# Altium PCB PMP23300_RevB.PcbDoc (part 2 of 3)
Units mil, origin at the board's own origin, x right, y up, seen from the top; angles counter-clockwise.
Board outline 3834 x 2383 mil, 4 copper layers (Top Layer 1, Signal Layer 2, Signal Layer 3, Bottom Layer 1), stack 70.112 mil thick; 203 components, 126 nets, 635 pads, 226 vias.
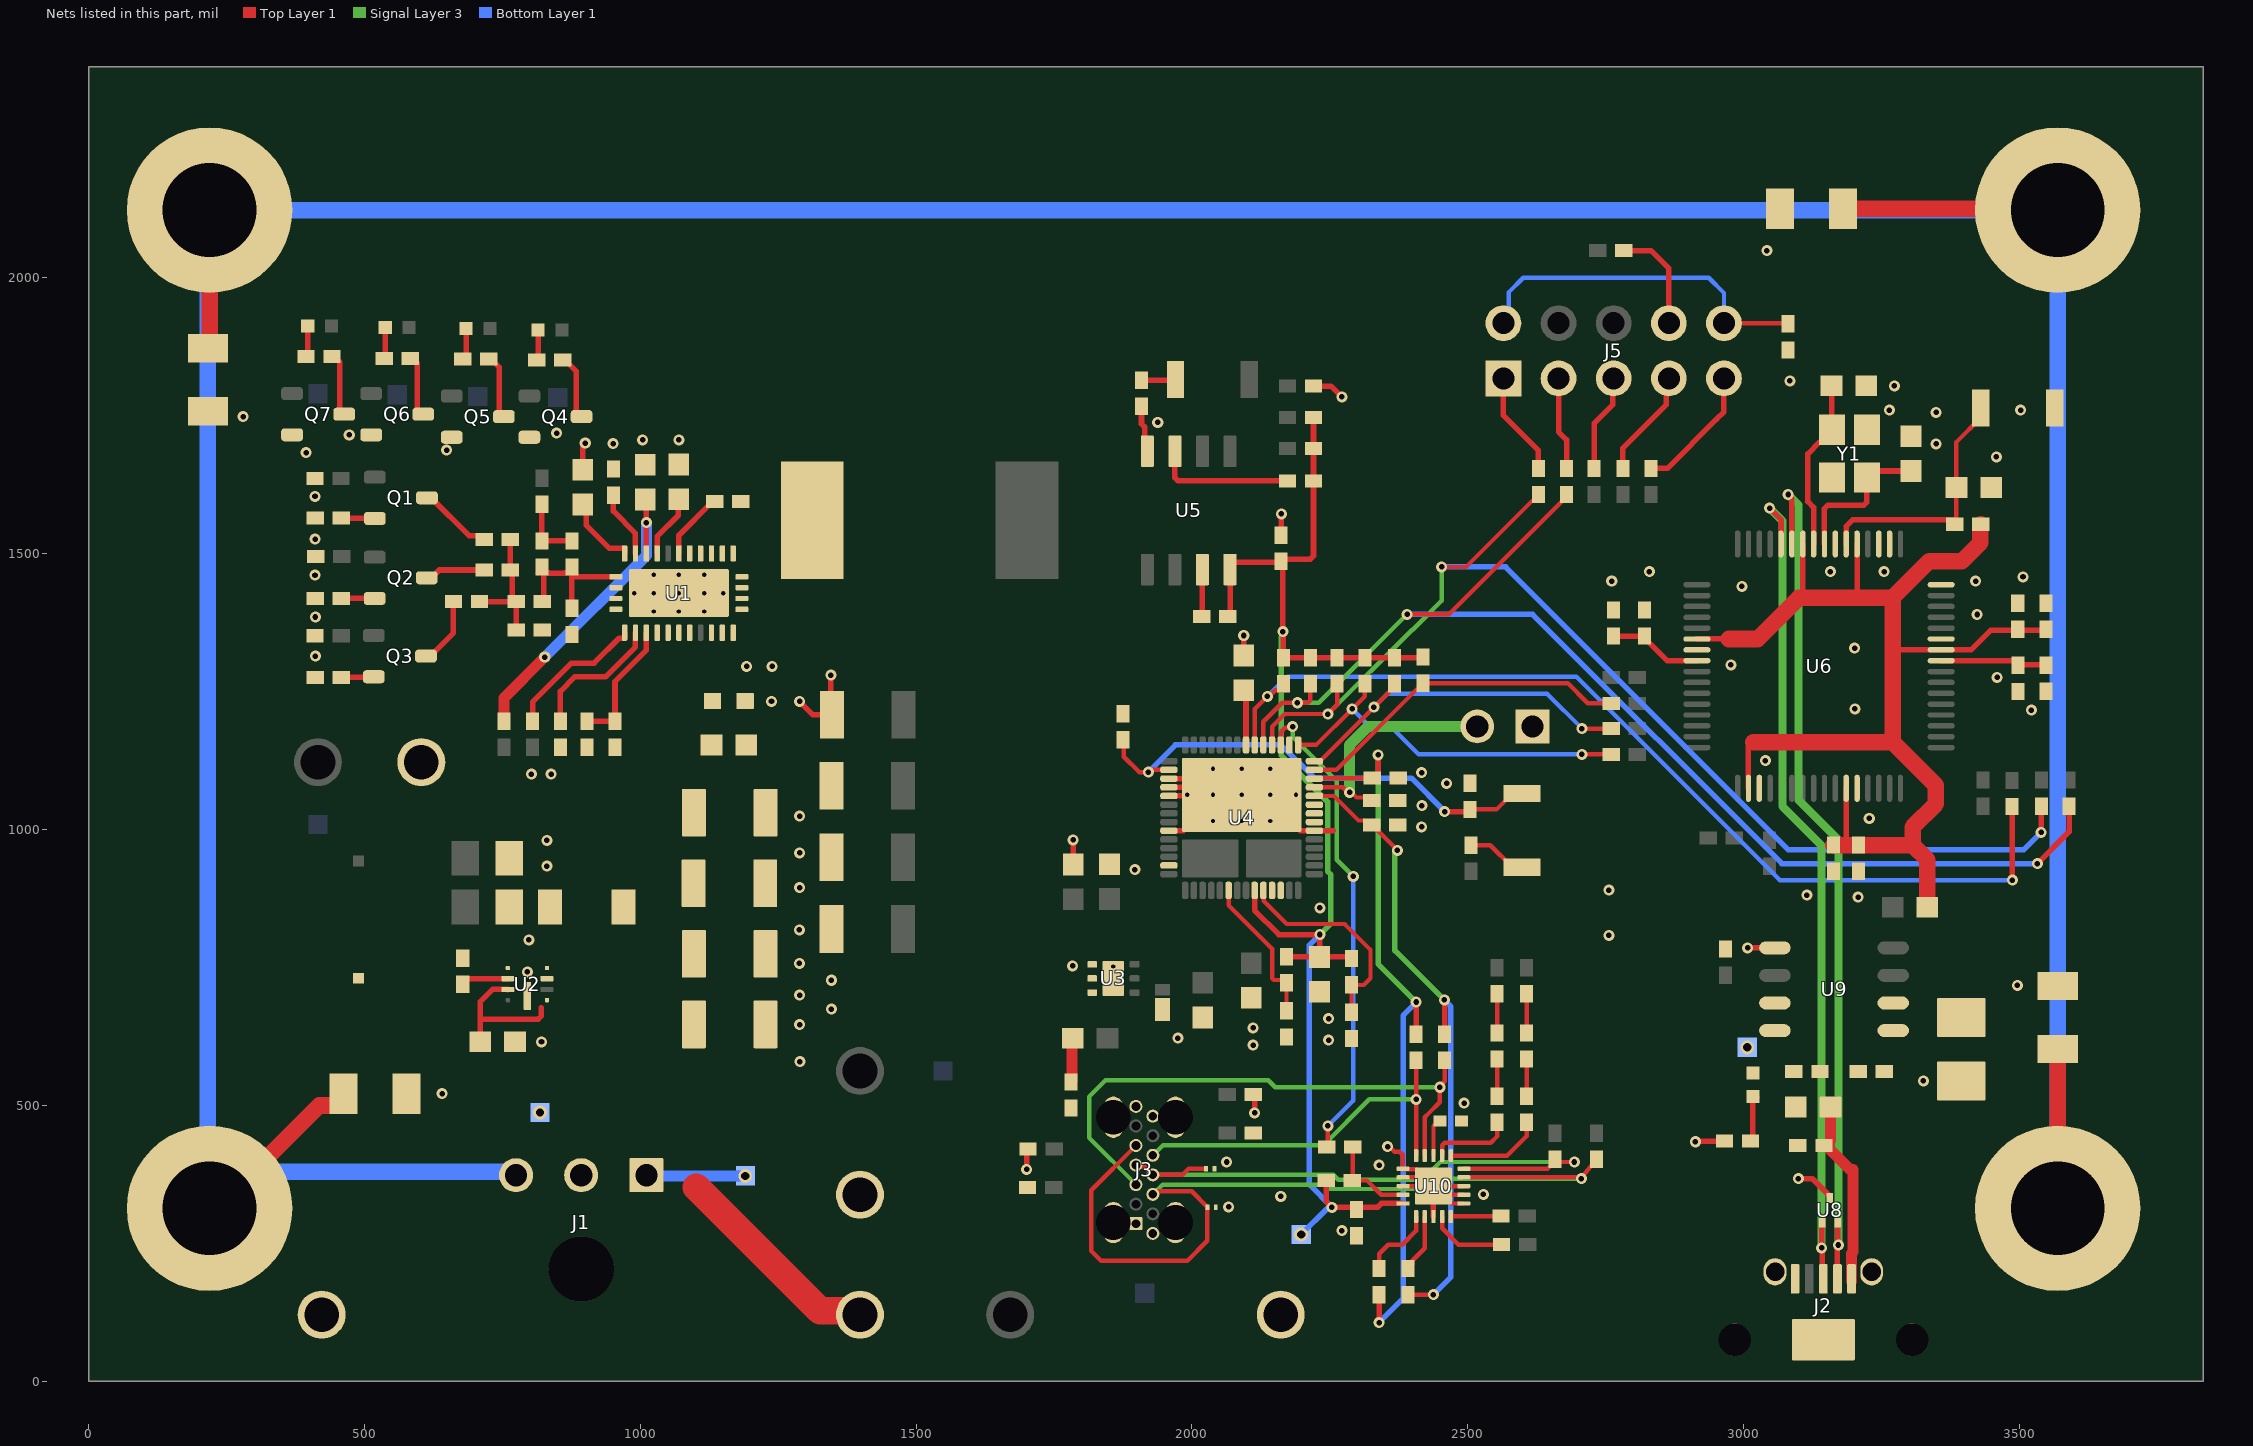
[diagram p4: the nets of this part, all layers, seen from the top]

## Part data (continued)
C21: library part CMP-0007357-5, "CAP, CERM, 4.7 uF, 35 V, +/- 10%, X5R, 0603", Cap_Case=0603, Manufacturer=MuRata, Supplier Part Number 1=490-7205-1-ND, TempCo=X5R, Tolerance_%=10%, Value1=Unknown, Value2=35V, ValueDisplayed=4.7uF
C22 C49 C54 C55: library part CMP-0006355-2, "CAP, CERM, 0.01 uF, 50 V, +/- 10%, C0G/NP0, 0402", Cap_Case=0402, Manufacturer=MuRata, Supplier Part Number 1=490-4762-1-ND, TempCo=C0G/NP0, Tolerance_%=10%, Value1=Unknown, Value2=50V, ValueDisplayed=0.01uF
C23 C24: library part CMP-0860558-1, "CAP, CERM, 220 pF, 50 V,+/- 10%, X7R, 0402", Cap_Case=0402, Manufacturer=Yageo, TempCo=X7R, Tolerance_%=10%, Value2=50V, ValueDisplayed=220pF
C25: library part CMP-0006355-1, "CAP, CERM, 0.01 uF, 50 V, +/- 10%, C0G/NP0, 0402", Cap_Case=0402, Manufacturer=MuRata, Supplier Part Number 1=490-4762-1-ND, TempCo=C0G/NP0, Tolerance_%=10%, Value1=Unknown, Value2=50V, ValueDisplayed=0.01uF
C26: library part CMP-0006228-2, "CAP, CERM, 0.1 uF, 16 V, +/- 10%, X7R, 0402", Cap_Case=0402, Manufacturer="Wurth Elektronik", Supplier Part Number 1=732-7532-1-ND, TempCo=X7R, Tolerance_%=10%, Value1=Unknown, Value2=16V, ValueDisplayed=0.1uF
C27 C28 C29 C30 C32 C34 C43 C53: library part CMP-0006356-2, "CAP, CERM, 0.1 uF, 50 V, +/- 10%, X7R, AEC-Q200 Grade 1, 0402", Cap_Case=0402, Manufacturer=MuRata, Supplier Part Number 1=490-10672-1-ND, TempCo=X7R, Tolerance_%=10%, Value1=Unknown, Value2=50V, ValueDisplayed=0.1uF
C31 C33: library part CMP-0006269-2, "CAP, CERM, 4.7 uF, 10 V, +/- 20%, X5R, 0402", Cap_Case=0402, Manufacturer=TDK, Supplier Part Number 1=445-8023-1-ND, TempCo=X5R, Tolerance_%=20%, Value1=Unknown, Value2=10V, ValueDisplayed=4.7uF
C35 C37: library part CMP-0007069-4, "CAP, CERM, 10 pF, 50 V, +/- 5%, C0G/NP0, AEC-Q200 Grade 1, 0603", Cap_Case=0603, Manufacturer=TDK, Supplier Part Number 1=445-5628-1-ND, TempCo=C0G/NP0, Tolerance_%=5%, Value1=Unknown, Value2=50V, ValueDisplayed=10pF
C36: library part CMP-0006770-3, "CAP, CERM, 180 pF, 50 V, +/- 5%, C0G/NP0, 0603", Cap_Case=0603, Manufacturer=AVX, Supplier Part Number 1=478-1178-1-ND, TempCo=C0G/NP0, Tolerance_%=5%, Value1="0.09 ohm", Value2=50V, ValueDisplayed=180pF
C42: library part CMP-0006236-2, "CAP, CERM, 0.01 uF, 50 V, +/- 5%, X7R, 0402", Cap_Case=0402, Manufacturer=Kemet, Supplier Part Number 1=399-7758-1-ND, TempCo=X7R, Tolerance_%=5%, Value1=Unknown, Value2=50V, ValueDisplayed=0.01uF
C44: library part CMP-0011512-2, "CAP, TA, 10 uF, 10 V, +/- 10%, 2.5 ohm, SMD", Cap_Case=B, Manufacturer=Vishay-Sprague, Supplier Part Number 1=718-1122-1-ND, Tolerance_%=10%, Value1="2.5 ohm", Value2=10V, ValueDisplayed=10uF
C45: library part CMP-0078623-1, "CAP, CERM, 10 µF, 10 V,+/- 20%, X5R, 0402", Cap_Case=0402_080, Manufacturer=AVX, Supplier Part Number 1=478-10052-1-ND, TempCo=X5R, Tolerance_%=20%, Value2=10V, ValueDisplayed=10µF
C46: library part CMP-0007508-5, "CAP, CERM, 1 uF, 50 V, +/- 10%, X7R, 0603", Cap_Case=0603, Manufacturer="Taiyo Yuden", Supplier Part Number 1=587-3247-1-ND, TempCo=X7R, Tolerance_%=10%, Value1=Unknown, Value2=50V, ValueDisplayed=1uF
C47: library part CMP-0007503-4, "CAP, CERM, 4.7 uF, 6.3 V, +/- 10%, X7R, 0603", Cap_Case=0603, Manufacturer="Taiyo Yuden", TempCo=X7R, Tolerance_%=10%, Value1=Unknown, Value2=6.3V, ValueDisplayed=4.7uF
C48 C52: library part CMP-0007497-5, "CAP, CERM, 10 uF, 10 V, +/- 20%, X7R, 0603", Cap_Case=0603, Manufacturer=MuRata, Supplier Part Number 1=81-GRM188Z71A106MA3D, TempCo=X7R, Tolerance_%=20%, Value1=Unknown, Value2=10V, ValueDisplayed=10uF
C50: library part CMP-0006347-2, "CAP, CERM, 1 uF, 16 V, +/- 10%, X5R, 0402", Cap_Case=0402, Manufacturer="Taiyo Yuden", Supplier Part Number 1=587-3709-2-ND, TempCo=X5R, Tolerance_%=10%, Value1=Unknown, Value2=16V, ValueDisplayed=1uF
C51: library part CMP-0007344-5, "CAP, CERM, 10 uF, 25 V, +/- 20%, X5R, 0603", Cap_Case=0603, Manufacturer=MuRata, Supplier Part Number 1=490-7202-1-ND, TempCo=X5R, Tolerance_%=20%, Value1=Unknown, Value2=25V, ValueDisplayed=10uF
C56 C58 C59 C60: library part CMP-0009060-2, "CAP, CERM, 0.047 uF, 630 V, +/- 10%, X7T, 1206", Cap_Case=1206, TempCo=X7T, Tolerance_%=10%, Value1=Unknown, Value2=630V, ValueDisplayed=0.047uF
C57: library part CMP-0096605-1, "100 pF ±5% 100V Ceramic Capacitor X7R 0603 (1608 Metric)", Digikey Part Number=478-12671-1-ND, Manufacturer="KYOCERA AVX", Mouser Part Number=581-06031C101JAT2A, Operating Temperature Range="-55°C to +125°C", TempCo=15%, Temperature Characteristic=X7R, Tolerance_%=5%, ValueDisplayed=100pF
C61: library part CMP-0006717-2, "CAP, CERM, 0.47 uF, 6.3 V, +/- 10%, X7R, 0402", Cap_Case=0402, Manufacturer="Taiyo Yuden", Supplier Part Number 1=587-3765-1-ND, TempCo=X7R, Tolerance_%=10%, Value1=Unknown, Value2=6.3V, ValueDisplayed=0.47uF
D1 D2 D3 D4 D8: library part CMP-0002919-1, "LED, White, SMD", Color=White, Manufacturer=OSRAM, Supplier Part Number 1="LW QH8G-Q2S2-3K5L-1-ND", Value1=W, Value2=2.8V
D5 D6: library part CMP-0073601-1, "1-Channel ESD Protection Diode for USB Type-C and Thunderbolt 3, DPL0002A (X2SON-2)", Alternate Manufacturer="Texas Instruments", Alternate PartNumber=TPD1E01B04DPLT
D7: library part CMP-0028829-1, "Diode, Schottky, 30 V, 2 A, 2-XFDFN", Manufacturer="ON Semiconductor", Supplier Part Number 1=NSR20F30NXT5GOSCT-ND, Value1=2A, Value2=0.48V
H1 H2 H3 H4: library part CMP-0003617-1, "Machine Screw, Round, #4-40 x 1/4, Nylon, Philips panhead", Manufacturer="B&F Fastener Supply", Supplier Part Number 1=H542-ND
J1: library part CMP-0096579-1, "Conn Power HDR 3 POS 3mm Solder RA Thru-Hole 3 Terminal 1 Port Micro-Fit 3.0™ Frame", Current_A=8.5A, Digikey Part Number=WM1866-ND, Manufacturer=Molex, Mouser Part Number=538-43650-0301, Operating Temperature Range="-40°C to +125°C", Voltage_V=600V
J2: library part CMP-0094509-1, "USB - micro AB USB 2.0 Receptacle Connector 5 Position Surface Mount, Right Angle; Through Hole", Current_A=1.8A, Digikey Part Number=H125777CT-ND, Manufacturer=Hirose, Mouser Part Number=798-ZX62RD-AB-5P830, Operating Temperature Range="-30°C to +85°C", Voltage_V=30V
J3: library part CMP-0096733-1, "USB-C (USB TYPE-C) USB 2.0 Receptacle Connector 24 (14+10 Dummy) Position Through Hole, Right Angle", Current_A=3A, Digikey Part Number=664-12402054M611A-ND, Manufacturer="Amphenol ICC", Mouser Part Number=523-12402054M611A, Operating Temperature Range=to
J4: library part CMP-0075626-1, "Header, 100mil, 2x1, Gold, TH", Color=Black, Manufacturer=Samtec
J5: library part CMP-0054550-1, "Header, 100mil, 5x2, Tin, TH", Color=Black, Current_A=3A, Manufacturer="Sullins Connector Solutions", Supplier Part Number 1=S2012E-05-ND, Voltage_V=1.8kV
L1: library part CMP-0064540-1, "Inductor, Shielded Drum Core, Ferrite, 33 uH, 4.2 A, 0.0368 ohm, SMD", Manufacturer="Wurth Elektronik", Supplier Part Number 1=732-1244-1-ND, Value1="0.0368 ohm", Value2=4.2A, ValueDisplayed=33uH
L2: library part CMP-0064421-1, "Inductor, Shielded Drum Core, Ferrite, 18 uH, 1.1 A, 0.088 ohm, SMD", Manufacturer="Wurth Elektronik", Supplier Part Number 1=732-1046-1-ND, Value1="0.088 ohm", Value2=1.1A, ValueDisplayed=18uH
L3: library part CMP-0003354-2, "Ferrite Bead, 26 ohm @ 100 MHz, 6 A, 0603", Manufacturer=MuRata, Supplier Part Number 1=490-3995-1-ND, Value1="0.007 ohm", Value2=6A, ValueDisplayed="26 ohm"
LBL1: library part CMP-0003625-1, "Thermal Transfer Printable Labels, 0.650\" W x 0.200\" H - 10,000 per roll", Manufacturer=Brady, Supplier Part Number 1=97C5133
Logo1: library part CMP-0074835-1, "IEC 61010-1 High Voltage Warning"
Logo2: library part CMP-0074837-2, "IEC 61010-1 Hot Surface Warning", Manufacturer="Texas Instruments"
Logo3: library part CMP-0074844-1
Logo4: library part CMP-0074769-1
Logo5: library part CMP-0074838-1, "Texas Instrument Corporate Signature"
Logo6: library part CMP-0074847-1, "FCC_disclaimer"
Q1 Q2 Q3 Q4 Q5 Q6 Q7: library part CMP-0000205-2, "MOSFET, N-CH, 20 V, 1.05 A, SOT-23", Alternate Manufacturer=None, Manufacturer=Nexperia, Supplier Part Number 1=568-6215-1-ND, Value1=0, Value2="3.9 nC"
R1: library part CMP-0026279-2, "RES, 300 k, 1%, 0.063 W, AEC-Q200 Grade 0, 0402", Manufacturer=Vishay-Dale, Power_W=63mW, Supplier Part Number 1=541-300KLCT-ND, TempCo="100 ppm/C", Tolerance_%=1%, Value2=0.063W, Value_Code=300k
R2 R4 R9 R14 R15 R16: library part CMP-0081856-1, "RES, 0, 0%, 0.2 W, AEC-Q200 Grade 0, 0402", Manufacturer=Vishay-Dale, Power_W=200mW, Supplier Part Number 1=541-0.0YBTR-ND, Tolerance_%=0%, Value2=0.2W, Value_Code=0
R3 R6 R8 R11 R12 R13: library part CMP-0026745-1, "RES, 100 k, 1%, 0.063 W, 0402", Manufacturer="Samsung Electro-Mechanics", Power_W=63mW, Supplier Part Number 1=1276-3432-1-ND, TempCo="100 ppm/C", Tolerance_%=1%, Value2=0.063W, Value_Code=100k
R5: library part CMP-0025993-3, "RES, 12.7 k, 1%, 0.063 W, AEC-Q200 Grade 0, 0402", Manufacturer=Vishay-Dale, Power_W=63mW, Supplier Part Number 1=541-12.7KLCT-ND, TempCo="100 ppm/C", Tolerance_%=1%, Value2=0.063W, Value_Code=12k7, ValueDisplayed=12.7k
R7 R17 R19 R23 R24 R25 R29 R30 R31 R34 R43 R44 R47 R48 R49 R50 R51 R52 R53 R54 R62 R65 R66 R67 R78 R80 R81 R82 R83 R84: library part CMP-0027004-2, "RES, 0, 5%, 0.063 W, 0402", Manufacturer="Yageo America", Power_W=63mW, Supplier Part Number 1=311-0.0JRCT-ND, TempCo="200 ppm/C", Tolerance_%=5%, Value2=0.063W, Value_Code=0000, ValueDisplayed=0
R10: library part CMP-0026196-2, "RES, 24.9 k, 1%, 0.063 W, AEC-Q200 Grade 0, 0402", Manufacturer=Vishay-Dale, Power_W=63mW, Supplier Part Number 1=541-24.9KLCT-ND, TempCo="100 ppm/C", Tolerance_%=1%, Value2=0.063W, Value_Code=24k9, ValueDisplayed=24.9k
R18 R32 R45 R46: library part CMP-0025950-3, "RES, 100 k, 1%, 0.063 W, AEC-Q200 Grade 0, 0402", Manufacturer=Vishay-Dale, Power_W=63mW, Supplier Part Number 1=541-100KLCT-ND, TempCo="100 ppm/C", Tolerance_%=1%, Value2=0.063W, Value_Code=100k
R20 R21 R27 R28: library part CMP-0026339-2, "RES, 3.83 k, 1%, 0.063 W, AEC-Q200 Grade 0, 0402", Manufacturer=Vishay-Dale, Power_W=63mW, Supplier Part Number 1=541-3.83KLCT-ND, TempCo="100 ppm/C", Tolerance_%=1%, Value2=0.063W, Value_Code=3k83, ValueDisplayed=3.83k
R22 R26 R35 R36 R37 R38 R57: library part CMP-0026658-1, "RES, 10.0 k, 1%, 0.1 W, 0402", Manufacturer=Panasonic, Power_W=100mW, Supplier Part Number 1=P10.0KLCT-ND, TempCo="100 ppm/C", Tolerance_%=1%, Value2=0.1W, Value_Code=10k0, ValueDisplayed=10.0k
R33: library part CMP-0026063-3, "RES, 191 k, 1%, 0.063 W, AEC-Q200 Grade 0, 0402", Manufacturer=Vishay-Dale, Power_W=63mW, Supplier Part Number 1=541-191KLCT-ND, TempCo="100 ppm/C", Tolerance_%=1%, Value2=0.063W, Value_Code=191k
R39 R40 R41 R42: library part CMP-0026918-5, "RES, 3.3 k, 5%, 0.063 W, AEC-Q200 Grade 0, 0402", Manufacturer=Vishay-Dale, Power_W=63mW, Supplier Part Number 1=541-3.3KJCT-ND, TempCo="200 ppm/C", Tolerance_%=5%, Value2=0.063W, Value_Code=3k30, ValueDisplayed=3.3k
R59: library part CMP-0022234-4, "RES, 249 k, 1%, 0.1 W, AEC-Q200 Grade 0, 0603", Manufacturer=Vishay-Dale, Power_W=100mW, Supplier Part Number 1=541-249KHCT-ND, TempCo="100 ppm/C", Tolerance_%=1%, Value2=0.1W, Value_Code=249k
R60 R69 R71: library part CMP-0026740-1, "RES, 4.99 k, 1%, 0.063 W, 0402", Manufacturer="Yageo America", Power_W=63mW, Supplier Part Number 1=311-4.99KLRCT-ND, TempCo="100 ppm/C", Tolerance_%=1%, Value2=0.063W, Value_Code=4k99, ValueDisplayed=4.99k
R61: library part CMP-0026822-3, "RES, 0, 5%, 0.063 W, AEC-Q200 Grade 0, 0402", Manufacturer=Vishay-Dale, Power_W=63mW, Supplier Part Number 1=541-0.0JCT-ND, TempCo="200 ppm/C", Tolerance_%=5%, Value2=0.063W, Value_Code=0000, ValueDisplayed=0
R68: library part CMP-0026359-2, "RES, 3.48, 1%, 0.063 W, AEC-Q200 Grade 0, 0402", Manufacturer=Vishay-Dale, Power_W=63mW, Supplier Part Number 1=541-3.48LLCT-ND, TempCo="100 ppm/C", Tolerance_%=1%, Value2=0.063W, Value_Code=3R48, ValueDisplayed=3.48
R70: library part CMP-0026092-3, "RES, 1.65 k, 1%, 0.063 W, AEC-Q200 Grade 0, 0402", Manufacturer=Vishay-Dale, Power_W=63mW, Supplier Part Number 1=541-1.65KLCT-ND, TempCo="100 ppm/C", Tolerance_%=1%, Value2=0.063W, Value_Code=1k65, ValueDisplayed=1.65k
R72 R73 R74 R75 R76 R77: library part CMP-0027007-2, "RES, 0, 5%, 0.063 W, AEC-Q200 Grade 0, 0402", Manufacturer="KOA Speer", Power_W=63mW, Supplier Part Number 1=660-RK73Z1ETTP, TempCo=ppm/C, Tolerance_%=5%, Value2=0.063W, Value_Code=0000, ValueDisplayed=0
R79: library part CMP-0026162-2, "RES, 20.0 k, 1%, 0.063 W, AEC-Q200 Grade 0, 0402", Manufacturer=Vishay-Dale, Power_W=63mW, Supplier Part Number 1=541-20.0KLCT-ND, TempCo="100 ppm/C", Tolerance_%=1%, Value2=0.063W, Value_Code=20k0, ValueDisplayed=20.0k
R85: library part CMP-0025958-3, "RES, 10.0 k, 1%, 0.063 W, AEC-Q200 Grade 0, 0402", Manufacturer=Vishay-Dale, Power_W=63mW, Supplier Part Number 1=541-10.0KLCT-ND, TempCo="100 ppm/C", Tolerance_%=1%, Value2=0.063W, Value_Code=10k0, ValueDisplayed=10.0k
S1 S2 S3: library part CMP-0002150-2, "SWITCH TACTILE SPST-NO 0.05A 12V", CurrentRating_mA=50A, Manufacturer="Omron Electronic Components", Supplier Part Number 1=SW1020CT-ND
TP1 TP2 TP6 TP8: library part CMP-0055147-2, "Test Point, Multipurpose, Red, TH", Color=Red, Manufacturer="Keystone Electronics", PartNumber=5010, Supplier Part Number 1=36-5010-ND
TP3 TP4 TP7 TP11: library part CMP-0055148-2, "Test Point, Multipurpose, Black, TH", Color=Black, Manufacturer="Keystone Electronics", PartNumber=5011, Supplier Part Number 1=36-5011-ND
TP5 TP9 TP10 TP12 TP15 TP17 TP18 TP19 TP20 TP21 TP22: library part CMP-0075188-1, "Test Lead clips and hooks, SMT", Current_A=2A, Manufacturer=Harwin, Supplier Part Number 1=S1751-46-ND
U1: library part CMP-0861019-1, "3.5V to 60V 5A Synchronous Step-Down Voltage Regulator, RNP0030A (WQFN-30)", Alternate Manufacturer="Texas Instruments"
U2: library part CMP-0750092-1, "LMR36503/06-Q1 Wide Input 60-V Synchronous, DC-DC Buck Converter, RPE0009A (VQFN-9)", Alternate Manufacturer="Texas Instruments", Alternate PartNumber=LMR36506R3RPER
U3: library part CMP-0077834-1, "22-V Precision Surge Protection Clamp, DRV0006A (WSON-6)", Alternate Manufacturer="Texas Instruments"
U4: library part CMP-0081032-2, "USB Type-C and USB PD Controller with Integrated Power Switches, RSH0056E (VQFN-56)", Alternate Manufacturer="Texas Instruments", Alternate PartNumber=TPS65987DDHRSHT
U5: library part CMP-0005376-2, "3V, 8Mbit, Serial Flash Memory with Dual and Qual SPI, SOIC-8", Manufacturer=Winbond, Supplier Part Number 1=W25Q80DVSNIG-ND
U6: library part CMP-0029860-2, "Tiva C Series Microcontroller, 256 KB Flash, 32 KB SRAM, 12 Bit, 12 Channels, -40 to 105 degC, 64-Pin LQFP (PM), Green (RoHS & no Sb/Br), Tape and Reel", Alternate PartNumber=TM4C123GH6PMI7, Manufacturer="Texas Instruments", Temperature Range="-40 to 105 degC"
U8: library part CMP-0043102-2, "ESD Protection Array for High-Speed Data Interfaces, 2 Channels, -40 to +85 degC, 3-pin SOT (DRT), Green (RoHS & no Sb/Br)", Breakdown Voltage(Min)(V)=9, Differential Capacitance(pF)=0.01, IO Capacitance(Typ)(pF)=0.7, IO Leakage Current(nA)=10, Manufacturer="Texas Instruments"
U9: library part CMP-0036484-1, "Single Output Fast Transient Response LDO, 1 A, Fixed 3.3 V Output, 2.7 to 10 V Input, with Low IQ, 8-pin SOIC (D), -40 to 125 degC, Green (RoHS & no Sb/Br)", Manufacturer="Texas Instruments", Power Good=TRUE
U10: library part CMP-0081565-1, "USB Type-C Port Protector: Short-to-VBUS Overvoltage and IEC ESD Protection, RUK0020B (WQFN-20)", Alternate Manufacturer="Texas Instruments"
Y1: library part CMP-0004635-1, "Crystal, 16 MHz, 8pF, SMD", Frequency Stability=+/-30ppm, Frequency_Fixed=16MHz, Manufacturer=NDK, Supplier Part Number 1=644-1157-1-ND

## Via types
v1: diameter 20, hole 10, Top Layer 1 to Bottom Layer 1, tented top, 93 vias
v2: diameter 20, hole 10, Top Layer 1 to Bottom Layer 1, 67 vias
v3: diameter 19.68, hole 7.87, Top Layer 1 to Bottom Layer 1, 29 vias
v4: diameter 20, hole 10, Top Layer 1 to Bottom Layer 1, tented both sides, 20 vias
v5: diameter 25, hole 15, Top Layer 1 to Bottom Layer 1, 8 vias
v6: diameter 19.68, hole 7.87, Top Layer 1 to Bottom Layer 1, tented both sides, 6 vias
v7: diameter 25, hole 15, Top Layer 1 to Bottom Layer 1, tented top, 3 vias

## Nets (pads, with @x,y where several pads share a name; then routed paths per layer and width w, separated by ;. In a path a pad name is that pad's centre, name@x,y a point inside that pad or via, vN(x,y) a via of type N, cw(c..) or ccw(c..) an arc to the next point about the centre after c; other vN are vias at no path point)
/FLT: R18.1 R19.1 U10.9 | length 164.3
  Top Layer 1 w8: R19.1@2292.11,424.22 2292.11,365 R18.1@2290.74,363.62 2317.65,363.62 2343.62,337.66 U10.9@2383.1,337.66
/FLT_TPD: R19.2 U4.31 | length 876.5
  Top Layer 1 w8: U4.31@2161.32,1153.31 2162.16,1154.16 2162.16,1177.36 2169.54,1184.73 2181.3,1184.73 v2(2182.97,1186.41) ; R19.2@2244.87,424.22 2246.72,426.07 v1(2246.72,462.43)
  Signal Layer 3 w8: v2(2182.97,1186.41) 2182.97,1167.86 2262.91,1087.92 2262.91,945 v1(2292.79,915.13)
  Bottom Layer 1 w8: v1(2246.72,462.43) 2292.79,508.5 v1(2292.79,915.13)
/PGOOD: U4.55
ADCIN1: R46.2 R60.1 U4.6 | length 274.6
  Top Layer 1 w8: U4.6@2066.83,889.53 2066.83,862.33 2145.57,783.59 2145.57,730.02 2148.46,727.13 2166.73,727.13 2171.77,722.1 R46.2@2171.77,669.1
ADCIN2: R33.1 R45.2 U4.10 | length 379.6
  Top Layer 1 w8: U4.10@2129.82,889.53 2130.66,888.69 2130.66,870.3 2172.32,828.65 2277.03,828.65 2324.05,781.63 2324.05,730.3 2311.79,718.04 R33.1@2301.06,718.04 ; R45.2@2289.62,668.29 R33.1@2289.62,718.75
C_CC1: J3.A5 R73.2 U10.4 | length 1035.6
  Top Layer 1 w8: U10.4@2422.47,408.52 2422.47,478.34 2429.22,485.09 2449.72,505.58 v1(2449.72,532.62) 2449.72,534.37 2458.65,543.31 R73.2@2458.65,581.32
  Signal Layer 3 w8: J3.A5@1898.73,356.13 1813.79,441.07 1813.79,515.38 1843.51,545.11 2138.75,545.11 2151.24,532.62 v1(2449.72,532.62)
C_CC2: J3.B5 R72.2 U10.5 | length 692.1
  Top Layer 1 w8: U10.5@2406.72,408.52 R72.2@2406.72,581.32
  Signal Layer 3 w8: J3.B5@1929.44,409.28 1947.78,427.62 2238.78,427.62 2322,510.84 v1(2406.72,510.84)
C_SBU_N: R34.2 R74.1 | length 67.4
  Top Layer 1 w8: R34.2@2553.51,516.38 R74.1@2553.51,583.78
C_SBU_P: R29.2 R75.1 | length 67.4
  Top Layer 1 w8: R29.2@2607.18,516.38 R75.1@2607.18,583.78
C_USB_N: D5.2 J3.A7 J3.B7 R17.2 U10.19 | length 1683.5
  Top Layer 1 w8: J3.A7@1898.73,427 1817.68,345.95 1817.68,235.77 1835.4,218.06 1992.04,218.06 2028.24,254.26 2028.24,315.67 1999.75,344.15 1939.4,344.15 1933.67,338.41 J3.B7@1929.44,338.41 ; U10.19@2493.34,369.15 2707.43,369.15 R17.2@2733.79,401.92
  Signal Layer 3 w8: J3.B7@1929.44,338.41 1947.16,356.13 2241.11,356.13 2249.16,348.08 2424.85,348.08 2443.79,367.02 v1(2706.25,367.02)
C_USB_P: D6.2 J3.A6 J3.B6 R7.2 U10.20 | length 1126
  Top Layer 1 w8: J3.A6@1898.73,391.56 1901.72,388.58 1914.71,388.58 J3.B6@1929.44,373.85 1983.18,373.85 1994.23,384.9 D6.2@2025.83,384.9 ; U10.20@2493.34,384.9 2645.06,384.9 2657.25,397.09 v1(2693.88,397.09)
  Signal Layer 3 w8: J3.B6@1929.44,373.85 2256.89,373.85 2265.74,365 2418.32,365 2450.41,397.09 v1(2693.88,397.09)
CC1: C23.1 R24.1 R73.1 U4.24 | length 1161.5
  Top Layer 1 w8: U4.24@2222.34,1060.79 2257.81,1060.79 2280.55,1038.05 2302.25,1016.36 2313.75,1016.36 C23.1@2321.56,1008.55 ; C23.1@2326.37,1008.55 2330.31,1008.55 2338.12,1000.74 2338.12,997.06 v1@2370.65,964.52 ; R24.1@2387.38,152.29 R24.1@2391.79,156.7 v1(2438.22,156.7)
  Top Layer 1 w10: v1(2457.87,690.85) 2458.26,690.46 2458.26,628.95 R73.1@2458.65,628.56
  Signal Layer 3 w10: v1@2368.14,962.23 2368.14,780.58 v1(2457.87,690.85)
  Bottom Layer 1 w10: v1(2438.22,156.7) 2469.72,188.19 2469.72,679.01 v1(2457.87,690.85)
  other v1: 2372.95,962.23
CC2: C24.1 R25.1 R72.1 U4.26 | length 1349.1
  Top Layer 1 w8: U4.26@2222.34,1092.29 2223.18,1093.13 2320.48,1093.13 C24.1@2322.99,1095.64
  Top Layer 1 w10: C24.1@2322.99,1095.64 2333.47,1095.64 2337.78,1099.94 v1(2337.78,1135.39) ; v1(2339.79,105.99) R25.1@2339.79,156.7 ; R72.1@2406.72,628.56 v1(2406.72,687.21)
  Signal Layer 3 w10: v1(2337.78,1135.39) 2337.78,756.15 v1(2406.72,687.21)
  Bottom Layer 1 w10: v1(2339.79,105.99) 2383.15,149.34 2383.15,662.49 2406.72,686.07 v1(2406.72,687.21)
DP_SBU_N: R74.2 R76.1 | length 70.9
  Top Layer 1 w8: R74.2@2553.51,631.03 R76.1@2553.51,701.89
DP_SBU_P: R75.2 R77.1 | length 70.9
  Top Layer 1 w8: R75.2@2607.18,631.03 R77.1@2607.18,701.89
EGND: C56.2 C58.2 C59.2 C60.2 H1.1 H2.1 H3.1 H4.1 J1.3 | length 8587.7
  Top Layer 1 w20: C56.2@216.09,1872.47 C56.2@219.09,1875.47 ; C58.2@3189.43,2113.14 C58.2@3201.86,2125.57
  Top Layer 1 w30: H4.1@219.09,313.1 231.61,313.1 418.06,499.55 451.38,499.55 461.97,510.14 C60.2@461.97,520.97 ; C56.2@219.09,1875.47 H1.1@219.09,2123.1 ; C58.2@3201.86,2125.57 H2.1@3463.15,2125.57 ; H3.1@3570.09,313.1 C59.2@3570.09,601.91
  Bottom Layer 1 w20: H4.1@216.09,388.45 213.09,385.45 H4.1@219.21,379.33 ; H1.1@216.09,2120.1 H1.1@219.09,2123.1 ; J1.3@768.66,379.33 J1.3@774.78,373.2
  Bottom Layer 1 w30: H4.1@216.09,388.45 H1.1@216.09,2120.1 ; H1.1@219.09,2123.1 2610.38,2123.1 3510.19,2123.1 3570.09,2063.2 H3.1@3570.09,313.1 ; H4.1@219.21,379.33 J1.3@768.66,379.33
F_SYS_3V3: C27.1 C28.1 C29.1 C30.1 C44.1 C45.1 R59.2 R85.1 U6.2 U6.11 U6.26 U6.37 U6.42 U6.54 U9.5 U9.6 | length 2321.2
  Top Layer 1 w10: U6.54@2915.91,1345.42 2973.65,1345.42 ; U6.2@3009.41,1074.75 3009.41,1150.09 3017.69,1158.37 ; 3100.93,1420.14 3107.84,1427.05 U6.42@3107.84,1517.66 ; 3186.06,971.82 3186.58,972.34 U6.11@3186.58,1074.75 ; 3206.26,1420.14 U6.37@3206.26,1517.66 ; 3270.77,1326.86 3271.9,1325.73 U6.26@3358.82,1325.73 3412.99,1325.73 3448.41,1361.15 C28.1@3546.55,1361.15 ; C28.1@3546.64,1361.15 C28.1@3546.55,1361.15 ; C28.1@3548.57,1363.17 C28.1@3546.55,1361.15
  Top Layer 1 w30: 2973.65,1345.42 3026.21,1345.42 3100.93,1420.14 3206.26,1420.14 3270.77,1420.14 ; 3017.69,1158.37 3270.77,1158.37 ; C29.1@3163.37,971.82 3186.06,971.82 C30.1@3208.75,971.82 3307.12,971.82 ; R59.2@3333.77,858.79 3333.77,945.17 3307.12,971.82 ; R85.1@3430.4,1553.48 3429.65,1552.74 3429.65,1519.68 3396.34,1486.37 3337,1486.37 3270.77,1420.14 ; 3270.77,1158.37 3270.77,1326.86 3270.77,1420.14 ; 3270.77,1158.37 3349.23,1079.91 3349.23,1046.46 3307.12,1004.35 3307.12,971.82
F_USB_D_N: J2.2 U6.43 U8.2 | length 1592.6
  Top Layer 1 w10: v2@3081.09,1606.06 3088.15,1598.99 U6.43@3088.15,1517.66 ; J2.2@3170.38,180.32 3170.38,241.78 3172.49,243.89 v2(3172.49,246.6) ; v2@3171.13,246.6 U8.2@3171.13,280.67
  Top Layer 1 w15: v2@3081.09,1606.06 v2(3081.09,1607.41)
  Signal Layer 3 w15: v2(3081.09,1607.41) 3100.06,1588.44 3100.06,1053.06 3172.49,980.63 v2(3172.49,246.6)
F_USB_D_P: J2.3 U6.44 U8.1 | length 1557
  Top Layer 1 w10: v2(3047.75,1582.53) 3068.47,1561.81 U6.44@3068.47,1517.66 ; U8.1@3143.28,286.78 3142.64,286.14 3142.64,242.01 v2(3142,241.37) 3143.57,239.8 3143.57,186.82 J2.3@3145.15,185.25
  Signal Layer 3 w15: v2(3047.75,1582.53) 3070.89,1559.38 3070.89,1041.92 3142,970.81 v2(3142,241.37)
F_VBUS: C43.1 D8.1 L3.2 TP15.1 U9.3 U9.4 | length 6.5
  Top Layer 1 w20: C43.1@3086.08,559.39 3087.89,561.2 C43.1@3091.83,561.2
  other v7: 3007.18,604.94
GND: C1.2 C2.2 C3.2 C4.2 C5.2 C6.2 C8.1 C9.1 C10.1 C11.1 C12.2 C14.2 C15.2 C17.2 C18.2 C19.2 C20.2 C22.2 C23.2 C24.2 C25.2 C26.2 C27.2 C28.2 C29.2 C30.2 C31.2 C32.1 C33.2 C34.1 C35.1 C36.1 C37.1 C42.2 C43.2 C44.2 C45.2 C46.2 C47.2 C48.2 C49.2 C50.2 C51.2 C52.2 C53.2 C54.2 C55.2 C56.1 C57.1 C58.1 C59.1 C60.1 C61.2 D5.1 D6.1 D7.2 J1.2 J2.5 J2.6 J2.7 J2.8 J2.9 J2.10 J3.1 J3.2 J3.3 J3.4 J3.A1 J3.A12 J3.B1 J3.B12 J4.1 Q4.2 Q5.2 Q6.2 Q7.2 R5.1 R8.1 R9.2 R10.1 R11.1 R12.1 R13.1 R14.2 R15.2 R16.2 R32.1 R43.1 R44.1 R45.1 R46.1 R57.1 R61.2 R68.1 R78.1 R81.2 S3.2 TP3.1 TP4.1 TP7.1 TP11.1 TP12.1 U1.13 U1.14 U1.15 U1.19 U1.24 U1.25 U1.26 U1.27 U1.28 U1.29 U1.30 U1.31 U2.9 U3.1 U3.2 U3.3 U3.7@1857.8,729.86 U4.11 U4.12 U4.20 U4.45 U4.46 U4.47 U4.51 U4.59@2090.45,1062.76 U5.4 U6.3 U6.12 U6.27 U6.32 U6.34 U6.35 U6.39 U6.55 U8.3 U9.1 U10.6 U10.7 U10.8 U10.13 U10.16 U10.17 U10.18 U10.21@2438.22,353.4 Y1.2 Y1.4 | length 1532.1
  Top Layer 1 w8: v1(2355.05,425.16) 2358.3,425.16 2367.59,415.87 2376.72,415.87 2382.38,410.21 2382.38,384.96 2382.44,384.9 U10.6@2383.1,384.9 ; U10.8@2383.1,353.4 U10.21@2438.22,353.4 ; U10.7@2383.1,369.15 U10.21@2422.47,369.15 ; U10.6@2384.16,383.84 U10.21@2407.79,383.84 ; U10.21@2438.22,335.48 2440.39,337.66 U10.21@2453.97,337.66 ; U10.16@2493.34,321.91 2469.72,321.91 U10.21@2453.97,337.66 ; U10.17@2493.34,337.66 U10.21@2453.97,337.66 ; U10.18@2493.34,353.4 U10.21@2438.22,353.4 ; U10.21@2438.22,353.4 U10.21@2453.97,337.66
  Top Layer 1 w10: R13.1@406.41,1351.29 R13.1@410.35,1351.29 ; R12.1@410.23,1493.61 R12.1@411.71,1495.1 ; C15.2@895.72,1661.46 895.72,1693.43 900.25,1697.95 v1(900.25,1700.66) ; C14.2@1009.12,1661.46 C14.2@1009.12,1662.44 ; v1@1068.14,1704.53 v1(1070.06,1706.44) ; v2(1288.79,1232.14) 1312.7,1208.23 C2.2@1347.43,1208.23 1345.79,1209.87 v2(1345.79,1280.08) ; v1(1700.68,383.84) 1700.68,417.98 C49.2@1703.13,420.43 ; C51.2@1784.93,936.42 v1(1784.93,981.1) ; R43.1@1908.84,1767.6 1908.84,1735.27 1914.7,1729.41 1914.7,1691.49 U5.4@1919.33,1686.85 ; U4.51@1958.56,997.8 1984.15,997.8 2001.87,1015.52 v3(2038.48,1015.52) ; U4.47@1958.56,1060.79 1990.06,1060.79 v3(1992.03,1062.76) 1992.03,1071.7 1987.18,1076.54 U4.46@1958.56,1076.54 ; U4.45@1958.56,1092.29 2008.96,1092.29 v3(2038.48,1062.76) ; C47.2@2093.91,1315.52 2094.21,1315.82 v1(2094.21,1351.74) ; C54.2@2111.37,519.34 2114.07,516.64 v1(2114.07,486.3) ; v3(2142.42,1015.52) 2179.03,1015.52 2196.75,997.8 U4.20@2222.34,997.8 2256.92,997.8 ; C26.2@2162.05,1533.7 v1@2162.05,1572 ; R44.1@2220.71,1804.12 2252.42,1804.12 v1(2272.01,1784.53) ; C23.2@2373.61,1008.55 C23.2@2375.68,1006.48 ; v1@2414.76,1006.48 v1(2416.68,1004.56) ; U10.21@2422.47,369.15 U10.21@2438.22,353.4 ; U10.13@2438.22,298.29 U10.21@2438.22,335.48 ; v2(2913.02,433.79) 2913.62,434.39 2965.25,434.39 R57.1@2965.85,434.99 ; 2962.5,79.59 J2.8@2980.96,66.16 ; v2(3008.06,785.41) U9.1@3057.38,785.41 ; v1(3100.06,367.01) 3125.06,367.01 3156.16,335.91 3156.16,332.96 U8.3@3157.06,332.05 ; C45.2@3208.37,561.2 C45.2@3212.31,561.2
  other v1: 2272.01,272.47 2066.65,315.67 2161.32,334.87 2528.77,338.25 2339.79,391.56 2063.09,397.09 2493.89,503.86 2111.33,609.2 2248.05,617.88 1974.8,621.55 2111.37,640.1 2248.05,657 1783.81,752.69 2756.31,808.04 1896.86,927.07 830.76,933.65 830.76,980.44 2461.95,1083.76 802.74,1100.47 838.3,1100.47 2416.92,1103.23 3040.03,1124.94 3522.17,1216.3 2977.56,1298.45 411.11,1314.25 411.08,1385.3 410.23,1461.13 2829.72,1467.46 3158.1,1467.46 3255.39,1467.46 410.48,1526.31 2162.44,1572.39 410.23,1603.84 950.89,1699.67 1004.16,1706.44 1938.32,1738.09 279.74,1748.61
  other v2: 3326.51,544.04 1289.59,579.09 820.92,615.08 1288.79,646.09 1346.71,674.49 1288.79,699.74 1346.71,726.66 795.16,741.66 1288.66,757.1 797.98,799.9 1288.66,817.98 3208.37,877.42 3115.45,881 1288.79,894.61 1288.79,957.58 3228.37,1020.16 1288.79,1024.32 2417.04,1043.47 1237.97,1232.14 3460.31,1276 1193.03,1295.82 1238.9,1295.95 3423.96,1389.83 2761.5,1450.35 3421.44,1450.35 3507.17,1457.99 3458.72,1675.42 394.23,1683.43 648.89,1687.73 3349.71,1699.04 472.32,1715.61 848.4,1718.49 3349.71,1756.5 3264.8,1760.38 3502.79,1760.38 3274.08,1804.29 3084.35,1813.48 3042.79,2049.76
  other v3: 1857.8,751.51 2090.45,1015.52 2090.45,1062.76 2142.42,1062.76 2188.88,1062.76 2038.48,1110.01 2090.45,1110.01 2142.42,1110.01 1024.39,1395.18 1070.06,1395.18 1115.73,1395.18 989.35,1428.65 1024.39,1428.65 1070.06,1428.65 1115.73,1428.65 1150.77,1428.65 1024.39,1462.11 1070.06,1462.11 1115.73,1462.11
  other v4: 640.8,520.97 3496.83,717.35 2232.23,857.75 2756.31,890.11 3202.16,1218.61 3201.86,1328.84 2997.4,1440.87
  other v5: 818.3,486.87
GPIO_5/I2C3_SCL: U4.21
GPIO_6/I2C3_SDA: U4.22
GPIO_7/I2C3_IRQZ: U4.23
HPD: U4.30
HRESET: C25.1 R32.2 S1.1 U4.44 | length 888.4
  Top Layer 1 w8: C25.1@1874.88,1162.79 1876.82,1160.85 1876.82,1132.07 1904.83,1104.05 v2(1921.18,1104.05) 1924.43,1104.05 1928.42,1108.04 U4.44@1958.56,1108.04 ; R32.2@2504.51,1036.36 2552.54,1036.36 2581.41,1065.24 S1.1@2599.13,1065.24
  Top Layer 1 w10: v1(2458.65,1032.57) 2500.72,1032.57 R32.2@2504.51,1036.36
  Bottom Layer 1 w10: v2(1921.18,1104.05) 1970.44,1153.31 2162.16,1153.31 2222.34,1093.13 2398.09,1093.13 v1(2458.65,1032.57)
I2C1_IRQZ: R22.2 R82.2 U4.29 | length 683.9
  Top Layer 1 w8: U4.29@2192.81,1153.31 2225.44,1153.31 v4(2290.74,1218.61) 2313.42,1241.29 2313.42,1264.03 R22.2@2313.75,1264.35 ; v4(2707.43,1136.4) 2707.49,1136.33 2760.2,1136.33 R82.2@2760.26,1136.27
  Bottom Layer 1 w8: v4(2290.74,1218.61) 2322.93,1186.41 2361.29,1186.41 2411.3,1136.4 v4(2707.43,1136.4)
I2C1_SCL: R20.2 R83.2 U4.27 | length 620.6
  Top Layer 1 w8: U4.27@2222.34,1108.04 2261.78,1108.04 2407.4,1253.66 2411.34,1253.66 2419.15,1261.47 R20.2@2419.15,1265.41 2681.63,1265.41 2718.22,1228.82 R83.2@2760.26,1228.82
I2C1_SDA: R21.2 R84.2 U4.28 | length 672.5
  Top Layer 1 w8: U4.28@2222.34,1123.79 2224.25,1125.69 2234.25,1125.69 v4(2330.31,1221.75) 2359.78,1251.22 2359.78,1256.41 R21.2@2367.59,1264.23 ; v4(2707.51,1182.91) 2707.56,1182.96 2760.21,1182.96 R84.2@2760.26,1183.01
  Bottom Layer 1 w8: v4(2330.31,1221.75) 2354.41,1245.86 2644.55,1245.86 v4(2707.51,1182.91)
I2C2_IRQZ: R26.2 R48.2 U4.34 | length 1787.1
  Top Layer 1 w8: U4.34@2114.07,1153.31 2114.07,1218.45 v4(2136.92,1241.29) 2140.17,1241.29 2151.4,1252.53 R26.2@2169.19,1252.53
  Top Layer 1 w10: R48.2@3487.28,1041.61 3487.65,1041.24 3487.65,908.49 v4(3488.03,908.11)
  Bottom Layer 1 w8: v4(2136.92,1241.29) 2172.93,1277.3 2697.25,1277.3 3066.44,908.11 v4(3488.03,908.11)
I2C2_SCL: R28.2 R49.2 R51.2 U4.32 | length 2151.5
  Top Layer 1 w8: U4.32@2145.57,1153.31 2145.57,1186.41 2168.55,1209.39 v2(2246.72,1209.39) 2263.57,1226.24 R28.2@2263.57,1264.48 ; v2(2452.97,1475.99) 2497.19,1475.99 2616.86,1595.66 2620.8,1595.66 2628.61,1603.47 R51.2@2628.61,1607.41
  Top Layer 1 w10: v4(3540.09,994.72) 3540.44,995.08 3540.44,1042.11 R49.2@3540.79,1042.46
  Signal Layer 3 w8: v2(2246.72,1209.39) 2399.74,1362.41 2400.59,1362.41 2452.97,1414.78 v2(2452.97,1475.99)
  Bottom Layer 1 w10: v2(2452.97,1475.99) 2568.87,1475.99 3081.89,962.98 3508.34,962.98 v4(3540.09,994.72)
I2C2_SDA: R27.2 R50.2 R53.2 U4.33 | length 2279.2
  Top Layer 1 w8: U4.33@2129.82,1153.31 2129.82,1195.5 2164.1,1229.78 v1(2191.66,1229.78) 2210.43,1229.78 2215.12,1234.47 R27.2@2215.12,1264.48 ; v1(2390.36,1390.06) 2466.2,1390.06 2679.61,1603.47 R53.2@2679.61,1607.41
  Top Layer 1 w10: v1(2390.36,1390.06) v1@2390.81,1389.6 ; v4(3533.09,938.18) 3591,996.1 R50.2@3591,1042.46
  Signal Layer 3 w8: v1(2191.66,1229.78) 2230.08,1229.78 v1(2390.36,1390.06)
  Bottom Layer 1 w10: v1(2390.36,1390.06) 2617.87,1390.06 3069.87,938.06 3532.97,938.06 v4(3533.09,938.18)
LDO_1V8: C47.1 U4.35 | length 94.3
  Top Layer 1 w10: C47.1@2090.09,1248.39 2089.93,1248.55 C47.1@2093.91,1252.53 ; U4.35@2098.33,1153.31 C47.1@2098.33,1241.76
LDO_3V3: C26.1 C48.1 C50.1 R18.2 R20.1 R21.1 R22.1 R26.1 R27.1 R28.1 R33.2 R39.1 R40.1 R41.2 R42.1 R60.2 TP17.1 U4.9 U5.8 U10.10 | length 2638.5
  Top Layer 1 w10: R41.2@2065.23,1386.19 2069.33,1390.3 2069.33,1478.46 2075.55,1484.68 C26.1@2160.28,1484.68 ; U4.9@2114.07,889.53 2114.07,853.24 2158.04,809.28 2231.92,809.28 v1(2232.23,809.59) ; v1(2165.11,1358.69) 2165.11,1479.85 C26.1@2160.28,1484.68 ; v1@2165.51,1358.3 2165.51,1312.12 R26.1@2165.9,1311.72 R27.1@2215.12,1311.72 R28.1@2263.57,1311.72 2418.22,1311.72 R20.1@2419.15,1312.65 ; R60.2@2172,769.57 C48.1@2231.93,769.57 ; R40.1@2220.71,1747.03 R39.1@2220.71,1690.79 R42.1@2220.71,1631.99 2220.71,1496.24 2214.85,1490.38 2165.97,1490.38 C26.1@2161.66,1486.06 C26.1@2160.28,1484.68 ; v1@2231.93,809.29 2232.23,808.99 2232.23,769.87 C48.1@2231.93,769.57 ; R18.2@2243.49,363.62 2243.49,325.64 v1(2254.12,315.02) 2336.85,315.02 2343.74,321.91 U10.10@2383.1,321.91 ; R33.2@2289.62,769.57 C48.1@2231.93,769.57
  Signal Layer 3 w10: v1(2165.11,1358.69) 2163.2,1356.78 2163.2,1349.71 2162.44,1348.95 2162.44,1134.29 2246.39,1050.34 2246.39,924.12 2252.23,918.27 2252.23,829.59 v1(2232.23,809.59)
  Bottom Layer 1 w10: v5(2198.28,265.75) 2245.63,313.11 2252.2,313.11 v1(2254.12,315.02) 2213.18,355.95 2213.18,790.53 v1(2232.23,809.59)
NetC1_1: C1.1 U1.8 | length 114.5
  Top Layer 1 w10: U1.8@1030.69,1500.5 1030.69,1531.14 1068.86,1569.32 1068.86,1598 C1.1@1069.71,1598.85
NetC7_1: C7.1 R2.2 R6.2 | length 120.5
  Top Layer 1 w10: R2.2@821.8,1589.58 R6.2@821.8,1523.14 C7.1@875.82,1523.14
NetC7_2: C7.2 R6.1 R10.2 R69.1 U1.12 | length 281
  Top Layer 1 w10: R6.1@814.99,1465.74 821.8,1472.56 824.63,1469.73 R6.1@824.63,1469.13 ; R69.1@827.46,1418.42 824.63,1421.24 R6.1@824.63,1469.13 ; R10.2@875.82,1400.83 875.82,1458.18 ; U1.12@955.88,1458.18 875.82,1458.18 ; R6.1@824.63,1469.13 828.61,1465.15 834.33,1465.15 834.47,1465.01 863.15,1465.01 863.29,1465.15 869.01,1465.15 875.82,1471.96 C7.2@875.82,1475.89 875.82,1458.18
NetC8_2: C8.2 C9.2 C10.2 C11.2 C12.1 C17.1 C57.2 J1.1 R1.2 TP2.1 TP5.1 U1.20 U1.21 U1.22 U2.3 U2.4 | length 581.6
  Top Layer 1 w50: J1.1@1011,373.2 J1.1@1016.91,367.3 ; 1101.7,351.66 1326.02,127.33 1391.39,127.33 TP2.1@1398.47,120.25
  Bottom Layer 1 w10: v5(1190.54,371.77) TP5.1@1190.75,371.98
  Bottom Layer 1 w20: J1.1@1011,373.2 1012.33,371.88 TP5.1@1190.75,371.98
NetC13_1: C13.1 L1.1 U1.1 U1.2 U1.3 U1.4 U1.5
NetC13_2: C13.2 U1.6 | length 122.9
  Top Layer 1 w10: U1.6@1070.06,1500.5 1070.06,1533.48 1129.51,1592.93 1133.44,1592.93 C13.2@1134.82,1594.31
NetC14_1: C14.1 R4.2 U1.9 | length 565.5
  Top Layer 1 w10: C14.1@1009.12,1598.47 1011,1596.58 v1(1011,1556.48) U1.9@1011,1500.5 ; R4.2@753.03,1196.62 R4.2@753.06,1196.59
  Top Layer 1 w20: R4.2@753.03,1196.62 753.03,1238.63 v1(826.82,1312.42)
  Bottom Layer 1 w20: v1(826.82,1312.42) 1011,1496.6 v1(1011,1556.48)
NetC15_1: C15.1 U1.11 | length 136.2
  Top Layer 1 w10: C15.1@902.49,1591.7 902.49,1551.39 943.62,1510.26 971.55,1510.26 971.63,1510.19 U1.11@971.63,1500.5
NetC16_1: C16.1 L2.1 U2.5
NetC16_2: C16.2 U2.6 | length 87.8
  Top Layer 1 w10: C16.2@678.13,719.53 678.13,722.71 684.94,729.52 U2.6@759.89,729.52
NetC18_1: C18.1 U2.1 U2.7 | length 247.7
  Top Layer 1 w10: C18.1@709.81,627.39 709.81,656.08 ; U2.7@759.89,709.84 759.68,710.05 732.4,710.05 709.81,687.47 709.81,656.08 ; 820.8,676.58 820.8,661.94 814.94,656.08 709.81,656.08
NetC21_1: C21.1 R68.2 | length 80.6
  Top Layer 1 w20: R68.2@1781.26,542.2 1782.73,543.68 1782.73,620.07 C21.1@1784.21,621.55
NetC31_1: C31.1 C32.2 U6.25 | length 194.8
  Top Layer 1 w10: U6.25@3358.82,1306.05 3489.38,1306.05 3496.98,1298.45 3544.07,1298.45 C32.2@3548.57,1293.95
NetC33_1: C33.1 C34.2 U6.56 | length 171.7
  Top Layer 1 w10: C34.2@2765,1350.78 C33.1@2821.02,1350.78 2821.02,1346.85 2861.82,1306.05 U6.56@2915.91,1306.05
NetC35_2: C35.2 U6.41 Y1.1 | length 311.8
  Top Layer 1 w10: U6.41@3127.52,1517.66 3127.52,1584.01 3117.06,1594.48 3117.06,1680.91 3138.41,1702.27 3142.35,1702.27 3160.97,1720.89 Y1.1@3160.97,1724.83 3160.12,1725.67 C35.2@3160.12,1804.29
NetC36_2: C36.2 R85.2 S3.1 U6.38 | length 467.4
  Top Layer 1 w8: R85.2@3383.16,1553.48 3386.5,1556.83 3386.5,1561.81 C36.2@3386.5,1620 3386.5,1702.51 3430.58,1746.58 S3.1@3430.58,1764.3
  Top Layer 1 w10: U6.38@3186.58,1517.66 3186.58,1549.64 3198.75,1561.81 R85.2@3386.5,1561.81
NetC37_2: C37.2 U6.40 Y1.3 | length 275.6
  Top Layer 1 w10: U6.40@3147.21,1517.66 3147.21,1581.74 3153.07,1587.6 3218.1,1587.6 3223.96,1593.46 Y1.3@3223.96,1638.21 3235.77,1650.02 C37.2@3304.2,1650.02
NetC42_1: C42.1 J2.1 L3.1 | length 356.3
  Top Layer 1 w20: L3.1@3166.8,505.56 L3.1@3158.1,496.86 3158.1,434.94 3150.22,427.06 3193.89,383.4 3198.79,383.4 3198.79,234.36 3195.97,231.54 J2.1@3195.97,180.32
NetC53_1: C53.1 U10.3 | length 56.8
  Top Layer 1 w8: U10.3@2438.22,408.52 2438.28,408.59 2438.28,462.61 C53.1@2440.18,464.51
NetC61_1: C61.1 R69.2 R70.1 R71.2 R79.2 | length 235.9
  Top Layer 1 w10: R70.1@708.56,1413.01 708.73,1413.18 775.2,1413.18 R69.2@775.36,1413.34 ; R79.2@764.23,1525.63 R71.2@764.23,1470.52 768.17,1466.58 768.17,1420.16 774.98,1413.34 R69.2@775.36,1413.34 ; C61.1@775.36,1361.49 R69.2@775.36,1413.34
NetD1_2: D1.2 R35.2 | length 55.7
  Top Layer 1 w10: R35.2@812.47,1850.99 814.73,1853.25 D1.2@814.73,1905.78
NetD2_2: D2.2 R36.2 | length 57.8
  Top Layer 1 w10: R36.2@678.17,1853.25 684.07,1859.16 D2.2@684.07,1908.57
NetD3_2: D3.2 R37.2 | length 57
  Top Layer 1 w10: R37.2@535.66,1854.35 537.63,1856.32 D3.2@537.63,1910.52
NetD4_2: D4.2 R38.2 | length 56.7
  Top Layer 1 w10: R38.2@393.87,1857.65 397.11,1860.88 D4.2@397.11,1912.96
NetD8_2: D8.2 R57.2 | length 84.7
  Top Layer 1 w10: R57.2@3013.09,434.99 3017.21,439.11 D8.2@3017.21,515.47
  Top Layer 1 w20: D8.2@3017.21,515.47 D8.2@3019.02,513.66
NetJ4_2: J4.2 R78.2 U4.25 | length 442.8
  Top Layer 1 w8: U4.25@2222.34,1076.54 2222.47,1076.67 2273.62,1076.67 2283.02,1067.27 v1(2286.26,1067.27) 2289.51,1067.27 2298.75,1058.03 2318.25,1058.03 R78.2@2323.85,1052.43
  Signal Layer 3 w20: v1(2286.26,1067.27) 2286.26,1153.04 2319.63,1186.41 2517.2,1186.41 J4.2@2517.67,1186.88
NetJ5_1: J5.1 R51.1 | length 189.7
  Top Layer 1 w10: J5.1@2565,1818 2565,1751.01 2628.61,1687.4 R51.1@2628.61,1654.65
NetJ5_2: J5.2 J5.10 R81.1 | length 640.9
  Top Layer 1 w8: J5.10@2965,1918 R81.1@3078.33,1918
  Bottom Layer 1 w8: J5.2@2565,1918 2574.48,1927.48 2574.48,1973.76 2601.25,2000.54 2937.22,2000.54 2965,1972.76 J5.10@2965,1918
NetJ5_3: J5.3 R53.1 | length 169.4
  Top Layer 1 w10: J5.3@2665,1818 2665,1720.89 2679.61,1706.28 R53.1@2679.61,1654.65
NetJ5_5: J5.5 R54.1 | length 178
  Top Layer 1 w10: R54.1@2729.61,1654.65 2729.61,1736.49 2763.64,1770.52 2763.64,1816.64 J5.5@2765,1818
NetJ5_7: J5.7 R66.1 | length 197.9
  Top Layer 1 w10: R66.1@2781.61,1654.65 2781.61,1691.64 2860.48,1770.52 2860.48,1813.48 J5.7@2865,1818
NetJ5_8: J5.8 R62.2 | length 194.5
  Top Layer 1 w10: R62.2@2783.29,2049.76 2832.61,2049.76 2865,2017.36 J5.8@2865,1918
NetJ5_9: J5.9 R80.1 | length 235.7
  Top Layer 1 w10: R80.1@2832.61,1654.65 2862.47,1654.65 2951.71,1743.9 2965,1757.19 J5.9@2965,1818
NetQ1_2: Q1.2 R14.1 | length 61.1
  Top Layer 1 w10: R14.1@457.72,1564.42 457.92,1564.22 518.5,1564.22 Q1.2@518.7,1564.01
NetQ1_3: Q1.3 R79.1 | length 135.2
  Top Layer 1 w10: Q1.3@613.19,1601.41 621.06,1601.41 690.03,1532.44 710.18,1532.44 R79.1@716.99,1525.63
NetQ2_2: Q2.2 R15.1 | length 60.8
  Top Layer 1 w10: R15.1@457.72,1419.02 457.77,1418.97 518.39,1418.97 Q2.2@518.45,1418.92
NetQ2_3: Q2.3 R71.1 | length 109.9
  Top Layer 1 w10: Q2.3@612.93,1456.32 621.3,1456.32 635.5,1470.52 R71.1@716.99,1470.52
NetQ3_2: Q3.2 R16.1 | length 60
  Top Layer 1 w10: R16.1@457.72,1275.25 458.58,1276.11 516.11,1276.11 Q3.2@516.97,1276.97
NetQ3_3: Q3.3 R70.2 | length 123.9
  Top Layer 1 w10: Q3.3@611.46,1314.37 619.33,1314.37 661.32,1356.36 R70.2@661.32,1413.01
NetQ4_3: Q4.3 R35.1 | length 105.7
  Top Layer 1 w10: R35.1@859.71,1850.99 863.65,1850.99 884.09,1830.55 Q4.3@884.09,1757.68
NetQ5_3: Q5.3 R36.1 | length 103.4
  Top Layer 1 w10: R36.1@725.41,1853.25 729.35,1853.25 744.19,1838.41 Q5.3@744.19,1759.94
NetQ6_3: Q6.3 R37.1 | length 99.5
  Top Layer 1 w10: R37.1@582.91,1854.35 586.85,1854.35 595.69,1845.51 Q6.3@595.69,1762.41
NetQ7_3: Q7.3 R38.1 | length 101.4
  Top Layer 1 w10: R38.1@441.12,1857.65 445.06,1857.65 455.16,1847.54 Q7.3@455.16,1764.34
NetR1_1: R1.1 R5.2 U1.18 | length 234.2
  Top Layer 1 w10: R5.2@903.78,1196.59 R1.1@954.2,1196.59 954.2,1268.25 1011,1325.05 U1.18@1011,1356.8
NetR3_2: R3.2 U1.16 | length 259.2
  Top Layer 1 w10: R3.2@804.71,1196.59 804.71,1231.15 875.07,1301.51 916.35,1301.51 961.87,1347.04 971.55,1347.04 971.63,1347.11 U1.16@971.63,1356.8
NetR8_2: R8.2 U1.10 | length 122.5
  Top Layer 1 w10: R8.2@951.19,1606.34 951.19,1577.1 991.32,1536.97 U1.10@991.32,1500.5
NetR9_1: R9.1 U1.17 | length 249.3
  Top Layer 1 w10: R9.1@855.02,1196.59 855.02,1250.51 881.09,1276.59 936.73,1276.59 991.32,1331.18 U1.17@991.32,1356.8
NetR23_2: R23.2 U10.15 | length 91.8
  Top Layer 1 w8: U10.15@2469.72,298.29 2469.72,298.78 2469.78,298.85 2560.22,298.85 R23.2@2560.78,299.41
NetR24_2: R24.2 U10.12 | length 107.1
  Top Layer 1 w8: R24.2@2391.79,203.94 2399.6,211.75 2399.6,218.06 2422.47,240.93 U10.12@2422.47,298.29
NetR25_2: R25.2 U10.11 | length 136.8
  Top Layer 1 w8: R25.2@2339.79,203.94 2339.79,230.77 2356.28,247.25 2381.5,247.25 2406.72,272.47 U10.11@2406.72,298.29
NetR29_1: R29.1 U10.1 | length 177.2
  Top Layer 1 w8: U10.1@2469.72,408.52 2571.53,408.52 2607.18,444.17 R29.1@2607.18,469.13
NetR30_2: R30.2 U10.14 | length 141.4
  Top Layer 1 w8: U10.14@2453.97,298.29 2453.97,276.84 2483.55,247.25 R30.2@2561.63,247.25
NetR31_1: R31.1 S1.2 | length 109.2
  Top Layer 1 w8: R31.1@2506.48,971.4 2541.39,971.4 2581.41,931.38 S1.2@2599.13,931.38
NetR34_1: R34.1 U10.2 | length 150.7
  Top Layer 1 w8: U10.2@2453.97,408.52 2453.97,427.46 2458.65,432.14 2542.11,432.14 2553.51,443.54 R34.1@2553.51,469.13
NetR41_1: R41.1 U5.7 | length 84.7
  Top Layer 1 w10: R41.1@2017.98,1386.19 2019.33,1387.54 U5.7@2019.33,1470.32
NetR42_2: R42.2 U5.3 | length 255.6
  Top Layer 1 w10: U5.3@1969.33,1686.85 1969.33,1637.85 1975.19,1631.99 R42.2@2173.47,1631.99
NetR43_2: R43.2 S2.2 | length 62.1
  Top Layer 1 w10: R43.2@1908.84,1814.85 1969.4,1814.85 S2.2@1970.48,1815.93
